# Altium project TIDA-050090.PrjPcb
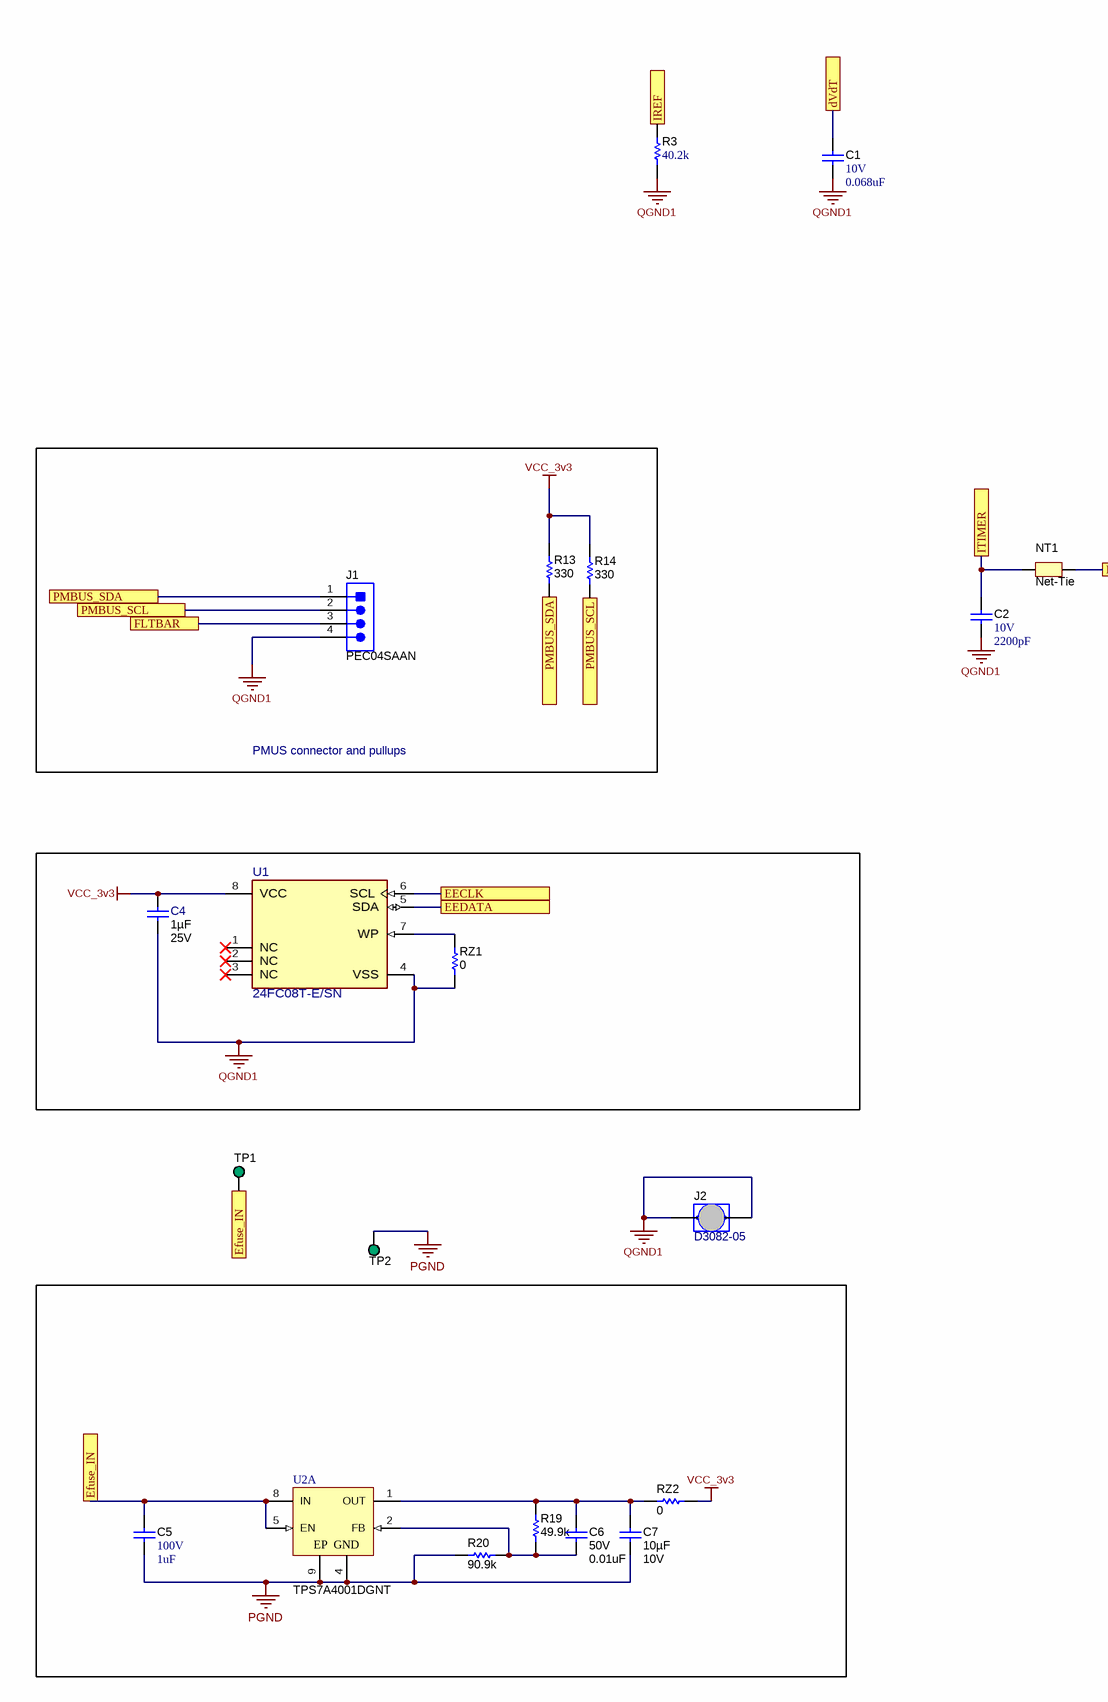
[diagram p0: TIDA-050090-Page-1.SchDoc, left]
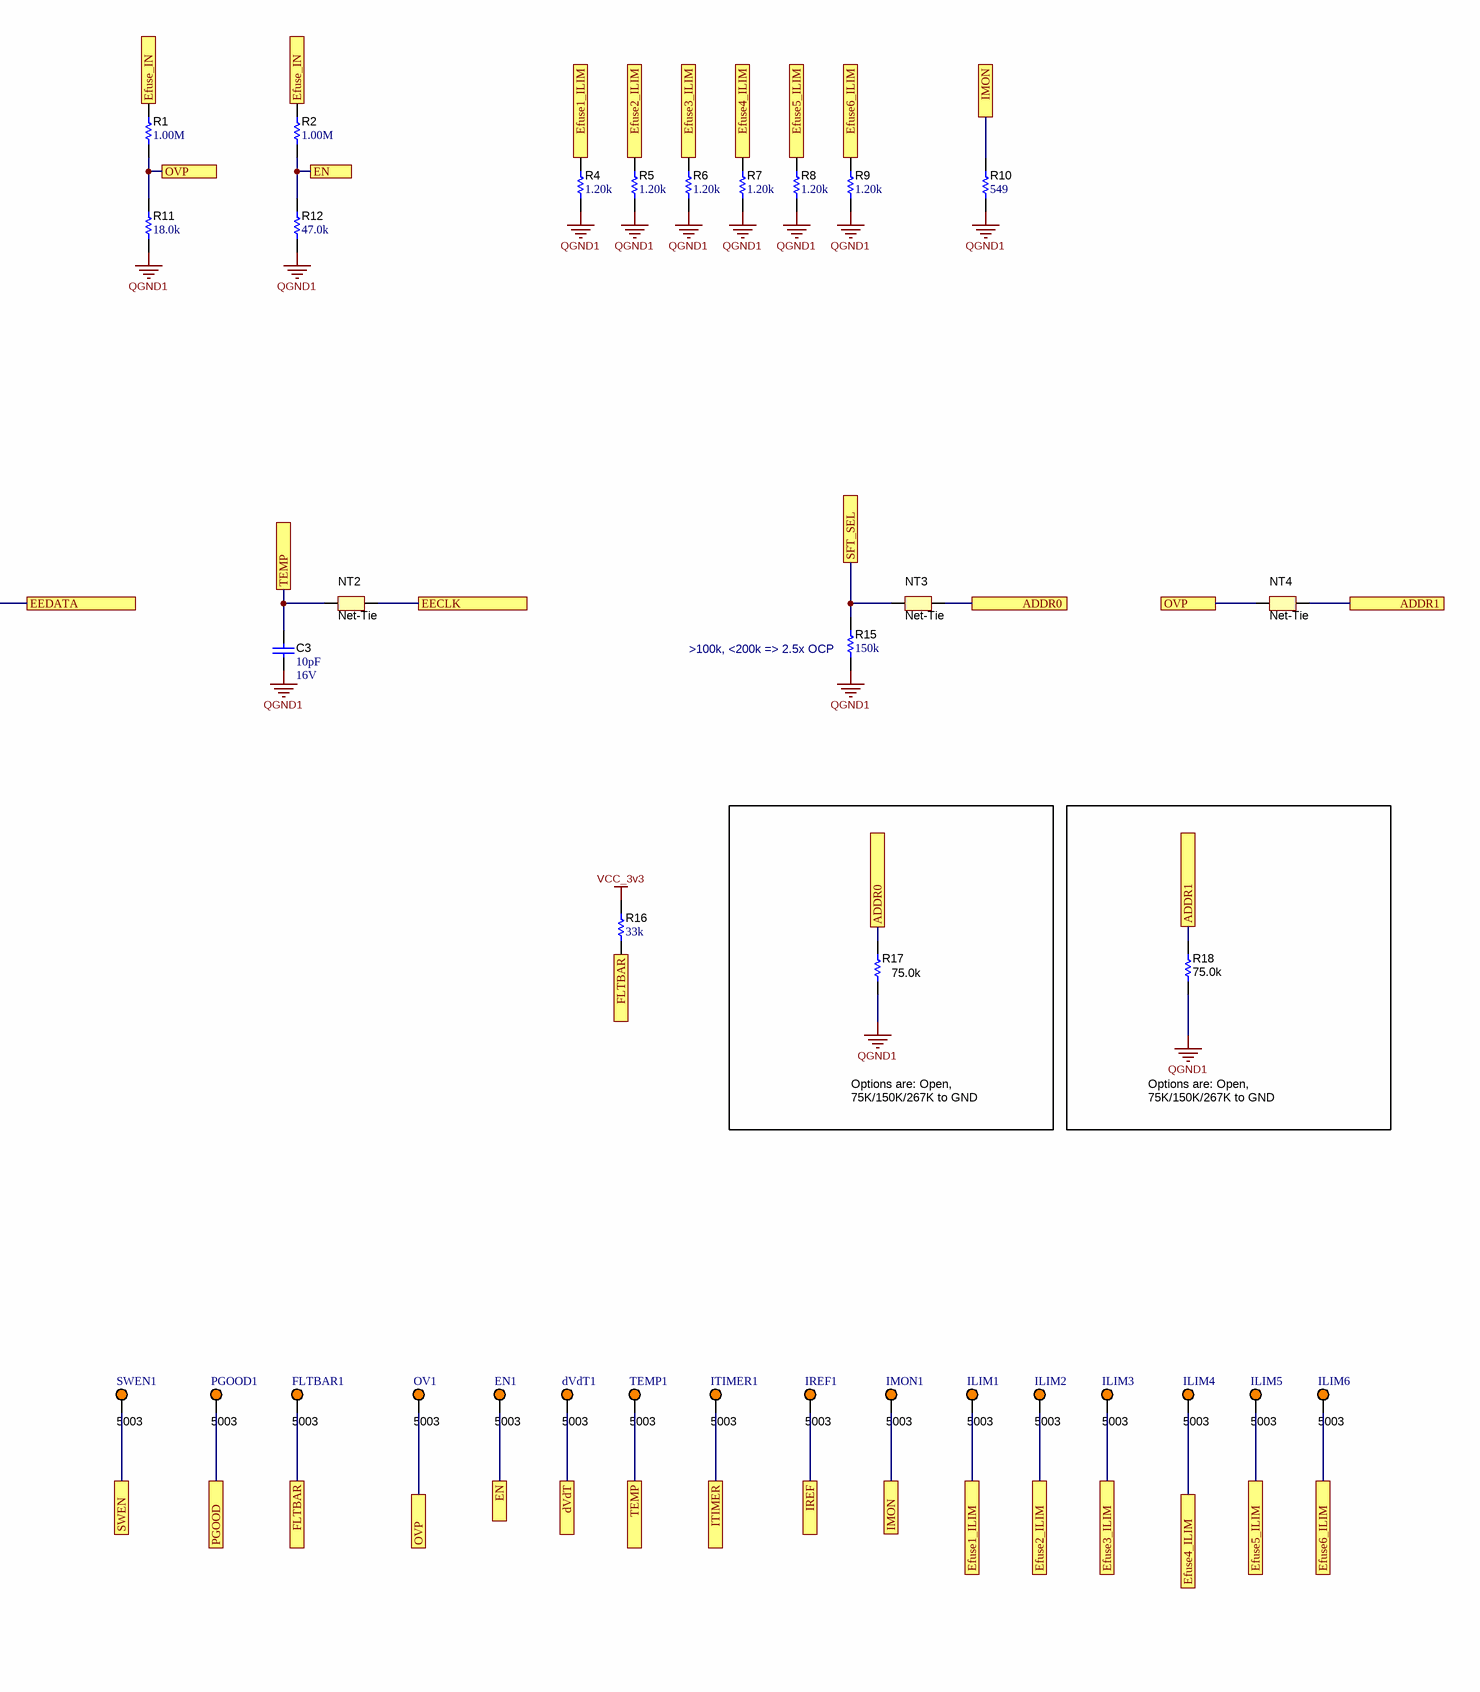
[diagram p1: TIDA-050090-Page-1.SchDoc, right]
CopyrightYear: 2024; PCB_Rev: A; PRJ_Customer: Public Release; PRJ_Engineer: Avishek Pal; PRJ_Number: TIDA-050090; PRJ_Title: TPS1689/5 Reference Design; SCH_Rev: A; TechSupport: http://www.ti.com/support; TID: 050090
3 sheets, 135 parts. Net scope: flat (ports and power ports of the same name join across sheets).
Board file: TIDA-050090.PcbDoc
Sheets:
  TIDA-050090-Page-1.SchDoc
  TIDA-050090-Page-2.SchDoc
  TIDA-050090-Hardware.SchDoc

## Sheet TIDA-050090-Page-1.SchDoc
size A2; Date: Not shown in title block; ApprovedBy: Not shown in title block; CheckedBy: Not shown in title block; Author: Not shown in title block; CompanyName: Not shown in title block; Engineer: Not shown in title block; Organization: Not shown in title block; Address1: Not shown in title block; Address2: Not shown in title block; Address3: Not shown in title block; Address4: Not shown in title block; DocumentNumber: 1; Revision: Use project parameter SCH_Rev; SheetNumber: 1; SheetTotal: 3; PageSetup: Record=PageOptions¦CenterHorizontal=True¦CenterVertical=True¦PrintScale=0.69¦XCorrection=1.00¦YCorrection=1.00¦PrintKind=0¦BorderSize=5000000¦LeftOffset=0¦BottomOffset=0¦Orientation=2¦PaperLength=1000¦PaperWidth=1000¦Scale=100¦PaperSource=15¦PrintQuality=600¦MediaType=1¦DitherType=10¦PaperKind=Letter¦PrintScaleMode=1

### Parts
C1  VDC_V: 10V  ValueDisplayed: 0.068uF  [0402]  (hidden comment: GRM155R61A683KA01D)
C2  VDC_V: 10V  ValueDisplayed: 2200pF  [0402]  (hidden comment: GRM155R61A222KA01D)
C3  Cap_F: 10pF  VDC_V: 16V  [0402]  (hidden comment: C0402C100K4GACTU)
C4  Cap_F: 1µF  VDC_V: 25V  [0603]  (hidden comment: GRJ188R71E105KE11D)
C5  VDC_V: 100V  ValueDisplayed: 1uF  [0805_HV]  (hidden comment: CGA4J3X7S2A105K125AB)
C6  VDC_V: 50V  ValueDisplayed: 0.01uF  [0402]  (hidden comment: GCM155R71H103KA55D)
C7  Cap_F: 10µF  VDC_V: 10V  [0805_HV]  (hidden comment: C0805C106J8RACAUTO)
dVdT1  5003  [Keystone5003]
EN1  5003  [Keystone5003]
FLTBAR1  5003  [Keystone5003]
ILIM1  5003  [Keystone5003]
ILIM2  5003  [Keystone5003]
ILIM3  5003  [Keystone5003]
ILIM4  5003  [Keystone5003]
ILIM5  5003  [Keystone5003]
ILIM6  5003  [Keystone5003]
IMON1  5003  [Keystone5003]
IREF1  5003  [Keystone5003]
ITIMER1  5003  [Keystone5003]
J1  PEC04SAAN  [SULLINS_PEC04SAAN]
J2  D3082-05  [Harwin_D3082-05]
NT1  Net-Tie  [Net-Tie_0805_HV_NoOverlay]  (net tie, no BOM)
NT2  Net-Tie  [Net-Tie_0805_HV_NoOverlay]  (net tie, no BOM)
NT3  Net-Tie  [Net-Tie_0805_HV_NoOverlay]  (net tie, no BOM)
NT4  Net-Tie  [Net-Tie_0805_HV_NoOverlay]  (net tie, no BOM)
OV1  5003  [Keystone5003]
PGOOD1  5003  [Keystone5003]
R1  ValueDisplayed: 1.00M  [0201]  (hidden comment: RK73H1HTTC1004F)
R2  ValueDisplayed: 1.00M  [0201]  (hidden comment: RK73H1HTTC1004F)
R3  ValueDisplayed: 40.2k  [0201]  (hidden comment: RC0201FR-0740K2L)
R4  ValueDisplayed: 1.20k  [0201]  (hidden comment: RC0201DR-071K2L)
R5  ValueDisplayed: 1.20k  [0201]  (hidden comment: RC0201DR-071K2L)
R6  ValueDisplayed: 1.20k  [0201]  (hidden comment: RC0201DR-071K2L)
R7  ValueDisplayed: 1.20k  [0201]  (hidden comment: RC0201DR-071K2L)
R8  ValueDisplayed: 1.20k  [0201]  (hidden comment: RC0201DR-071K2L)
R9  ValueDisplayed: 1.20k  [0201]  (hidden comment: RC0201DR-071K2L)
R10  ValueDisplayed: 549  [0201]  (hidden comment: RC0201FR-07549RL)
R11  ValueDisplayed: 18.0k  [0201]  (hidden comment: RC0201FR-0718KL)
R12  ValueDisplayed: 47.0k  [0201]  (hidden comment: RC0201FR-7D47KL)
R13  ValueDisplayed: 330  [0402]  (hidden comment: ERJ-2RKF3300X)
R14  ValueDisplayed: 330  [0402]  (hidden comment: ERJ-2RKF3300X)
R15  ValueDisplayed: 150k  [0201]  (hidden comment: RC0201FR-7D150KL)
R16  ValueDisplayed: 33k  [0201]  (hidden comment: RC0201JR-0733KL)
R17  ValueDisplayed: 75.0k  [0402]  (hidden comment: CRCW040275K0FKED)
R18  ValueDisplayed: 75.0k  [0402]  (hidden comment: CRCW040275K0FKED)
R19  ValueDisplayed: 49.9k  [0402]  (hidden comment: CRCW040249K9FKED)
R20  ValueDisplayed: 90.9k  [0402]  (hidden comment: CRCW040290K9FKED)
RZ1  ValueDisplayed: 0  [0402]  (hidden comment: CRCW04020000Z0ED)
RZ2  ValueDisplayed: 0  [0402]  (hidden comment: CRCW04020000Z0ED)
SWEN1  5003  [Keystone5003]
TEMP1  5003  [Keystone5003]
TP1  (no value)  [Keystone5126]
TP2  (no value)  [Keystone5126]
U1  24FC08T-E/SN  [FP-24FC08T-E_SN_SOIC8-MFG]
U2  TPS7A4001DGNT  [DGN0008B_N]  (part A of 2)

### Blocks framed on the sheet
PMUS connector and pullups: J1 R13 R14

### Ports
ADDR0, ADDR1, dVdT, EECLK, EEDATA, Efuse1_ILIM, Efuse2_ILIM, Efuse3_ILIM, Efuse4_ILIM, Efuse5_ILIM, Efuse6_ILIM, Efuse_IN, EN, FLTBAR, IMON, IREF, ITIMER, OVP, PGOOD, PMBUS_SCL, PMBUS_SDA, SFT_SEL, SWEN, TEMP

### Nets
PGND: C5.2 C7.2 R20.1 TP2.1 U2.4(GND) U2.9(EP)
QGND1: C1.2 C2.2 C3.2 C4.2 J1.4 J2.1 J2.2 R3.1 R4.1 R5.1 R6.1 R7.1 R8.1 R9.1 R10.1 R11.1 R12.1 R15.1 R17.1 R18.1 RZ1.1 U1.4(VSS)
VCC_3v3: C4.1 R13.2 R14.2 R16.2 RZ2.1 U1.8(VCC)
ADDR0: NT3.2 R17.2 ; port ADDR0
ADDR1: NT4.2 R18.2 ; port ADDR1
dVdT: C1.1 dVdT1.1 ; port dVdT
EECLK: NT2.2 U1.6(SCL) ; port EECLK
EEDATA: NT1.2 U1.5(SDA) ; port EEDATA
Efuse1_ILIM: ILIM1.1 R4.2 ; port Efuse1_ILIM
Efuse2_ILIM: ILIM2.1 R5.2 ; port Efuse2_ILIM
Efuse3_ILIM: ILIM3.1 R6.2 ; port Efuse3_ILIM
Efuse4_ILIM: ILIM4.1 R7.2 ; port Efuse4_ILIM
Efuse5_ILIM: ILIM5.1 R8.2 ; port Efuse5_ILIM
Efuse6_ILIM: ILIM6.1 R9.2 ; port Efuse6_ILIM
Efuse_IN: C5.1 R1.2 R2.2 TP1.1 U2.5(EN) U2.8(IN) ; port Efuse_IN
EN: EN1.1 R2.1 R12.2 ; port EN
FLTBAR: FLTBAR1.1 J1.3 R16.1 ; port FLTBAR
IMON: IMON1.1 R10.2 ; port IMON
IREF: IREF1.1 R3.2 ; port IREF
ITIMER: C2.1 ITIMER1.1 NT1.1 ; port ITIMER
OVP: NT4.1 OV1.1 R1.1 R11.2 ; port OVP
PGOOD: PGOOD1.1 ; port PGOOD
PMBUS_SCL: J1.2 R14.1 ; port PMBUS_SCL
PMBUS_SDA: J1.1 R13.1 ; port PMBUS_SDA
SFT_SEL: NT3.1 R15.2 ; port SFT_SEL
SWEN: SWEN1.1 ; port SWEN
TEMP: C3.1 NT2.1 TEMP1.1 ; port TEMP
NetC6_1: C6.1 C7.1 R19.2 RZ2.2 U2.1(OUT)
NetC6_2: C6.2 R19.1 R20.2 U2.2(FB)
NetRZ1_2: RZ1.2 U1.7(WP)

Not connected (* = marked no-connect by the designer): U1 1(NC)* 2(NC)* 3(NC)*

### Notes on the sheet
- (near R15) >100k, <200k => 2.5x OCP
- Options are: Open, 75K/150K/267K to GND

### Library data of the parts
C1 = CMP-0006585-2: CAP, CERM, 0.068 uF, 10 V, +/- 10%, X5R, 0402; Manufacturer: MuRata; TaMin_C: -55°C; Polarized: N; SizeAreaWB_mm2: 3; Value1: Unknown; U/M: EA; TaMax_C: 85°C; SizeZ_mm: 0.6; SizeX_mm: 1; SizeY_mm: 0.5; Cap_F: 68nF; AEC Category: Q200
C2 = CMP-0006569-2: CAP, CERM, 2200 pF, 10 V, +/- 10%, X5R, 0402; Manufacturer: MuRata; TaMin_C: -55°C; Polarized: N; SizeAreaWB_mm2: 3; Value1: Unknown; U/M: EA; Value: 2200pF; TaMax_C: 85°C; SizeZ_mm: 0.6; SizeX_mm: 1; SizeY_mm: 0.5; Cap_F: 2.2nF; AEC Category: Q200
C3 = CMP-0079539-1: CAP, CERM, 10 pF, 16 V,+/- 10%, C0G, 0402; Manufacturer: Kemet; SizeAreaWB_mm2: 3; SizeArea_mm2: 0.5; AEC Qualified: N; AEC Category: Q200; Value: 10pF; TaMax_C: 125°C; SizeZ_mm: 0.6; Green_REACh: Passed; TaMin_C: -55°C; Green_Lifecycle: Active; U/M: EA; SizeX_mm: 1
C4 = CMP-0079720-1: CAP, CERM, 1 µF, 25 V,+/- 10%, X7R, 0603; Manufacturer: MuRata; TaMin_C: -55°C; Polarized: N; SizeAreaWB_mm2: 4.68; U/M: EA; Value: 1uF; TaMax_C: 125°C; SizeZ_mm: 1; SizeX_mm: 1.6; SizeY_mm: 0.8; SizeArea_mm2: 1.28; AEC Category: Q200
C5 = CMP-0007980-1: CAP, CERM, 1 uF, 100 V, +/- 10%, X7S, AEC-Q200 Grade 1, 0805; Manufacturer: TDK; TaMin_C: -55°C; ESR_ohm: 8.255m; Polarized: N; SizeAreaWB_mm2: 6.75; Value1: 0.008255 ohm; U/M: EA; Value: 1uF; TaMax_C: 125°C; SizeZ_mm: 1.45; SizeX_mm: 2; SizeY_mm: 1.25; Cap_Case: 0805; SizeArea_mm2: 2.5; AEC Qualified: Y; Cap_F: 1µF; IRMS_A: 2.2744A; AEC Grade: 1; AEC Category: Q200
C6 = CMP-0006355-1: CAP, CERM, 0.01 uF, 50 V, +/- 10%, C0G/NP0, 0402; Manufacturer: MuRata; TaMin_C: -55°C; Polarized: N; SizeAreaWB_mm2: 3; Value1: Unknown; U/M: EA; Value: 0.01uF; TaMax_C: 125°C; SizeZ_mm: 0.6; SizeX_mm: 1; SizeY_mm: 0.5; Cap_F: 10nF; AEC Category: Q200
C7 = CMP-0081061-1: CAP, CERM, 10 µF, 10 V,+/- 5%, X7R, AEC-Q200 Grade 1, 0805; Manufacturer: Kemet; TaMin_C: -55°C; Polarized: N; SizeAreaWB_mm2: 6.75; U/M: EA; Value: 10uF; TaMax_C: 125°C; SizeZ_mm: 1.45; SizeX_mm: 2; SizeY_mm: 1.25; Cap_Case: 0805; SizeArea_mm2: 2.5; AEC Qualified: Y; AEC Grade: 1; AEC Category: Q200
dVdT1 EN1 FLTBAR1 ILIM1-ILIM6 IMON1 IREF1 ITIMER1 OV1 PGOOD1 SWEN1 TEMP1 = CMP-0055140-1: Test Point, Miniature, Orange, TH; Manufacturer: Keystone; CNHeader: FALSE; Green_Lifecycle: Active; Green_REACh: Passed; ContactFinish: Silver; CT: TRUE
J1 = CMP-0054562-1: Header, 100mil, 4x1, Tin, TH; Manufacturer: Sullins Connector Solutions; CNHeader: TRUE; Current_A: 3A; Green_Lifecycle: Not Set; Shrouded: N; Gender: Male; Green_REACh: Incomplete; Voltage_V: 1.8kV; Row_Count: 1; Pitch_mm: 2.54; CT: FALSE; Cert_UL: Y
J2 = CMP-0075110-1: 1mm Uninsulated Shorting Plug, 10.16mm spacing, TH; Manufacturer: Harwin; CNHeader: False; Green_Lifecycle: Active; Green_REACh: Passed; CompType: Jumper Wire
NT1-NT4 = CMP-0078142-6: Single point connection between nets.
R1 R2 = CMP-0028122-1: RES, 1.00 M, 1%, 0.05 W, AEC-Q200 Grade 0, 0201; Manufacturer: KOA Speer; Power_W: 50mW; TempCo: 200 ppm/C; Value_Code: 1M00; U/M: EA; Value: 1.00Meg; EIA_Code: E96; Res_ohm: 1M; SizeX_mm: 0.6; SizeY_mm: 0.3; SizeZ_mm: 0.26; Value2: 0.05W; SizeArea_mm2: 0.18; AEC Qualified: Y; VDC_V: 25V; AEC Grade: 0; AEC Category: Q200
R3 = CMP-0027688-1: RES, 40.2 k, 1%, 0.05 W, 0201; Manufacturer: Yageo America; Power_W: 50mW; TempCo: 200 ppm/C; Value_Code: 40k2; U/M: EA; Value: 40.2k; EIA_Code: E96; SizeX_mm: 0.6; SizeY_mm: 0.3; SizeZ_mm: 0.26; Value2: 0.05W; SizeArea_mm2: 0.18; AEC Qualified: N; VDC_V: 25V; AEC Category: Q200
R4-R9 = CMP-0028147-1: RES, 1.20 k, 0.5%, 0.05 W, 0201; Manufacturer: Yageo America; Power_W: 50mW; TempCo: 200 ppm/C; Value_Code: 1k20; U/M: EA; Value: 1.20k; EIA_Code: E192; Res_ohm: 1.2k; SizeX_mm: 0.6; SizeY_mm: 0.3; SizeZ_mm: 0.26; Value2: 0.05W; SizeArea_mm2: 0.18; AEC Qualified: N; VDC_V: 25V; AEC Category: Q200
R10 = CMP-0027769-1: RES, 549, 1%, 0.05 W, 0201; Manufacturer: Yageo America; Power_W: 50mW; TempCo: 200 ppm/C; Value_Code: 549R; U/M: EA; Value: 549; EIA_Code: E96; SizeX_mm: 0.6; SizeY_mm: 0.3; SizeZ_mm: 0.26; Value2: 0.05W; SizeArea_mm2: 0.18; AEC Qualified: N; VDC_V: 25V; AEC Category: Q200
R11 = CMP-0027410-1: RES, 18.0 k, 1%, 0.05 W, 0201; Manufacturer: Yageo America; Power_W: 50mW; TempCo: 200 ppm/C; Value_Code: 18k0; U/M: EA; Value: 18.0k; Res_ohm: 18k; SizeX_mm: 0.6; SizeY_mm: 0.3; SizeZ_mm: 0.26; Value2: 0.05W; SizeArea_mm2: 0.18; AEC Qualified: N; VDC_V: 25V; AEC Category: Q200
R12 = CMP-0028024-1: RES, 47.0 k, 1%, 0.05 W, 0201; Manufacturer: Yageo America; Power_W: 50mW; TempCo: 200 ppm/C; Value_Code: 47k0; U/M: EA; Value: 47.0k; Res_ohm: 47k; SizeX_mm: 0.6; SizeY_mm: 0.3; SizeZ_mm: 0.26; Value2: 0.05W; SizeArea_mm2: 0.18; AEC Qualified: N; VDC_V: 25V; AEC Category: Q200
R13 R14 = CMP-0026694-1: RES, 330, 1%, 0.1 W, AEC-Q200 Grade 0, 0402; Manufacturer: Panasonic; Power_W: 100mW; TempCo: 100 ppm/C; Value_Code: 330R; U/M: EA; Value: 330; SizeX_mm: 1; SizeY_mm: 0.5; SizeZ_mm: 0.6; Value2: 0.1W; AEC Qualified: Y; VDC_V: 50V; AEC Grade: 0; AEC Category: Q200
R15 = CMP-0027959-1: RES, 150 k, 1%, 0.05 W, 0201; Manufacturer: Yageo America; Power_W: 50mW; TempCo: 200 ppm/C; U/M: EA; Value: 150k; EIA_Code: E96; SizeX_mm: 0.6; SizeY_mm: 0.3; SizeZ_mm: 0.26; Value2: 0.05W; SizeArea_mm2: 0.18; AEC Qualified: N; VDC_V: 25V; AEC Category: Q200
R16 = CMP-0027101-1: RES, 33 k, 5%, 0.05 W, 0201; Manufacturer: Yageo America; Power_W: 50mW; TempCo: 200 ppm/C; Value_Code: 33k0; U/M: EA; Value: 33k; EIA_Code: E24; SizeX_mm: 0.6; SizeY_mm: 0.3; SizeZ_mm: 0.26; Value2: 0.05W; SizeArea_mm2: 0.18; AEC Qualified: N; VDC_V: 25V; AEC Category: Q200
R17 R18 = CMP-0026543-1: RES, 75.0 k, 1%, 0.063 W, 0402; Manufacturer: Vishay-Dale; Power_W: 63mW; TempCo: 100 ppm/C; Value_Code: 75k0; U/M: EA; Value: 75.0k; EIA_Code: E96; Res_ohm: 75k; SizeX_mm: 1; SizeY_mm: 0.5; SizeZ_mm: 0.6; Value2: 0.063W; VDC_V: 50V; AEC Category: Q200
R19 = CMP-0026403-1: RES, 49.9 k, 1%, 0.063 W, 0402; Manufacturer: Vishay-Dale; Power_W: 63mW; TempCo: 100 ppm/C; Value_Code: 49k9; U/M: EA; Value: 49.9k; EIA_Code: E96; SizeX_mm: 1; SizeY_mm: 0.5; SizeZ_mm: 0.6; Value2: 0.063W; VDC_V: 50V; AEC Category: Q200
R20 = CMP-0026605-1: RES, 90.9 k, 1%, 0.063 W, 0402; Manufacturer: Vishay-Dale; Power_W: 63mW; TempCo: 100 ppm/C; Value_Code: 90k9; U/M: EA; Value: 90.9k; EIA_Code: E96; SizeX_mm: 1; SizeY_mm: 0.5; SizeZ_mm: 0.6; Value2: 0.063W; VDC_V: 50V; AEC Category: Q200
RZ1 RZ2 = CMP-0026822-3: RES, 0, 5%, 0.063 W, AEC-Q200 Grade 0, 0402; Manufacturer: Vishay-Dale; Power_W: 63mW; TempCo: 200 ppm/C; Value_Code: 0000; Value: 0; EIA_Code: E24; SizeX_mm: 1; SizeY_mm: 0.5; SizeZ_mm: 0.6; Value2: 0.063W; AEC Qualified: Y; VDC_V: 50V; AEC Category: Q200
TP1 TP2 = CMP-0055158-1: Test Point, Multipurpose, Green, TH; Manufacturer: Keystone; CNHeader: FALSE; Green_Lifecycle: Active; Green_REACh: Passed; ContactFinish: Silver; CT: TRUE
U1 = CMP-0094711-2: EEPROM Memory IC 8Kb (1K x 8) I²C 1 MHz 450 µs 8-SOIC; Manufacturer: Microchip; Frequency_Fixed: 400kHz; SizeZ_mm: 1.75mm; Nominal Supply Current: 1-3mA; TaMax_C: +125°C; Min Supply Voltage: 1.7V; Access Time: 450ns; Interface: I2C; AEC Qualified: Yes; Standoff Height: 0.1mm; Memory Size: 8Kbits; TaMin_C: -40°C; Max Supply Voltage: 5.5V; AEC Grade: Grade 1
U2 = CMP-0035947-1: Single Output LDO, 50 mA, Adjustable 1.175 to 90 V Output, 7 to 100 V Input, 8-pin MSOP (DGN), -40 to 125 degC, Green (RoHS & no Sb/Br); Manufacturer: Texas Instruments; Vout Adj(Max)(V): 90; SubFamily: Single Channel LDO; Accuracy(%): 2.5; Vin(Min)(V): 7; Iout(Max)(A): 0.05; Vdo(Typ)(mV): 290; Vout Adj(Min)(V): 1.2; Vin(Max)(V): 100; Iq(Typ)(mA): 0.02

## Sheet TIDA-050090-Page-2.SchDoc
size A2; Date: Not shown in title block; ApprovedBy: Not shown in title block; CheckedBy: Not shown in title block; Author: Not shown in title block; CompanyName: Not shown in title block; Engineer: Not shown in title block; Organization: Not shown in title block; Address1: Not shown in title block; Address2: Not shown in title block; Address3: Not shown in title block; Address4: Not shown in title block; DocumentNumber: 2; Revision: Use project parameter SCH_Rev; SheetNumber: 2; SheetTotal: 3; PageSetup: Record=PageOptions¦CenterHorizontal=True¦CenterVertical=True¦PrintScale=0.69¦XCorrection=1.00¦YCorrection=1.00¦PrintKind=0¦BorderSize=5000000¦LeftOffset=0¦BottomOffset=0¦Orientation=2¦PaperLength=1000¦PaperWidth=1000¦Scale=100¦PaperSource=15¦PrintQuality=600¦MediaType=1¦DitherType=10¦PaperKind=Letter¦PrintScaleMode=1
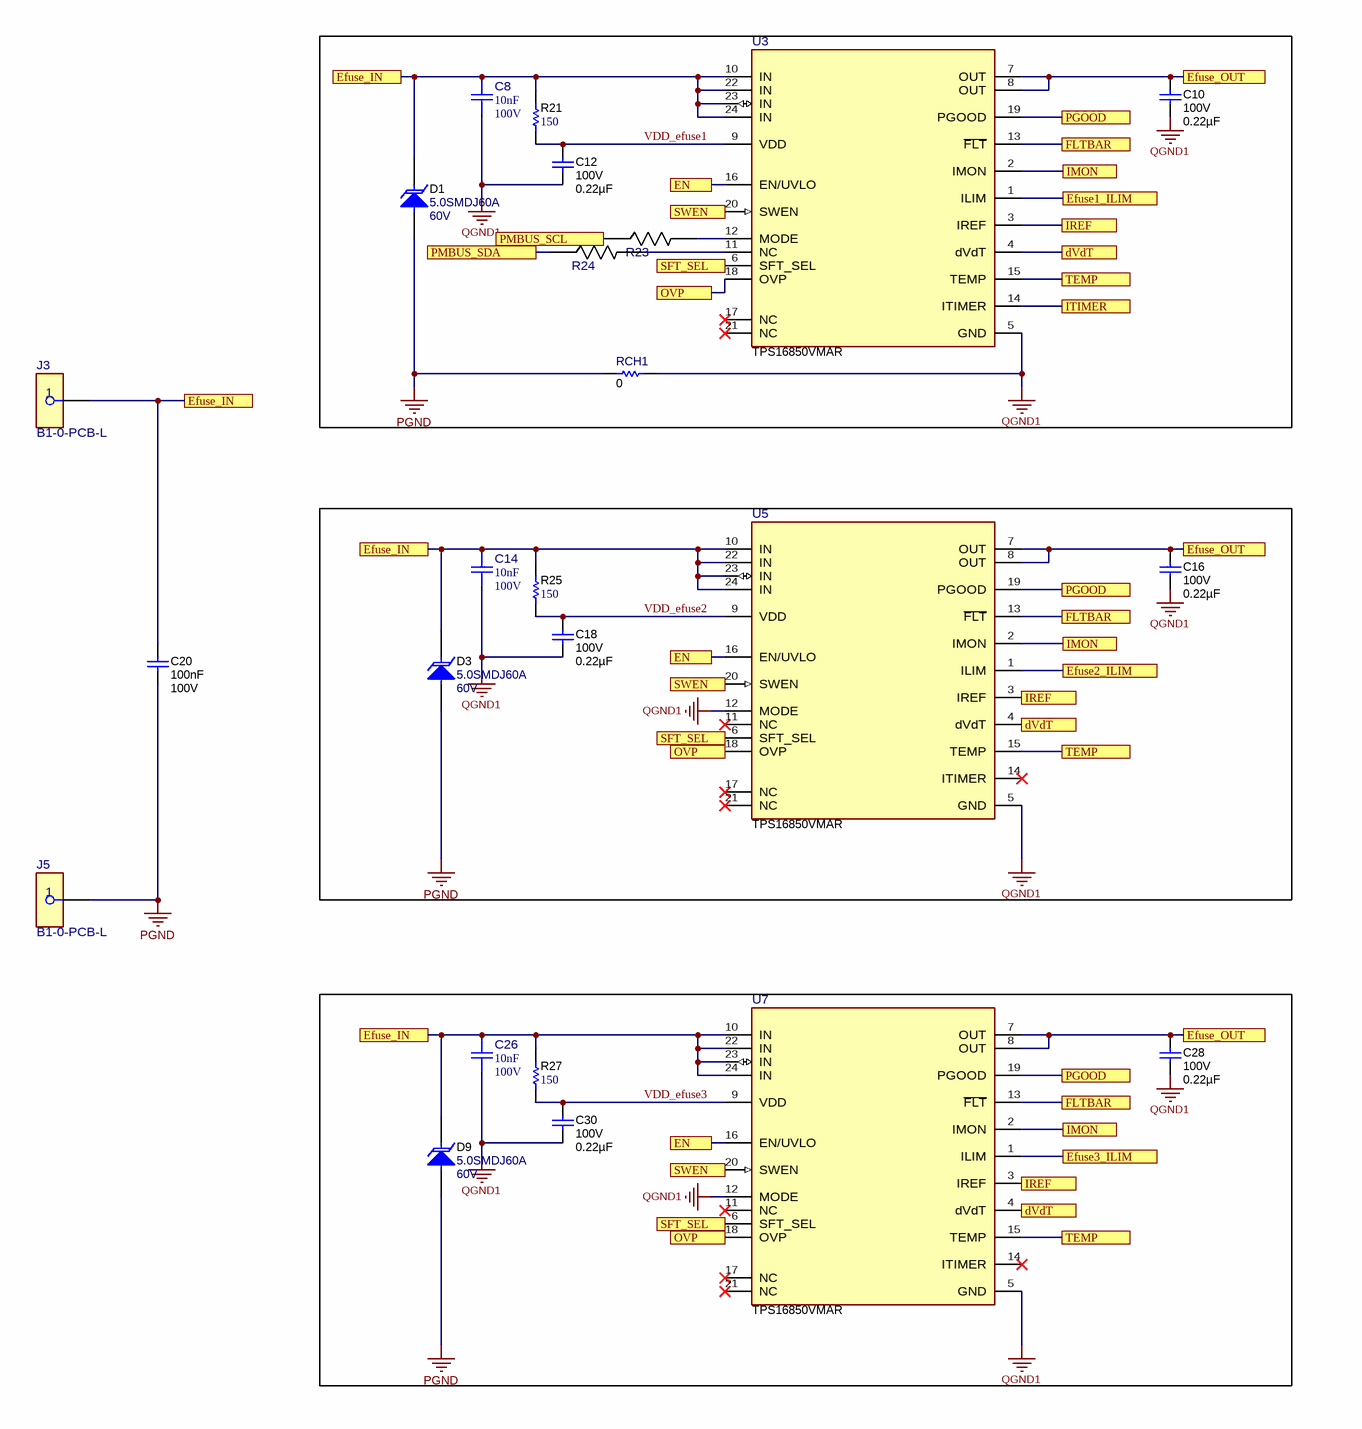
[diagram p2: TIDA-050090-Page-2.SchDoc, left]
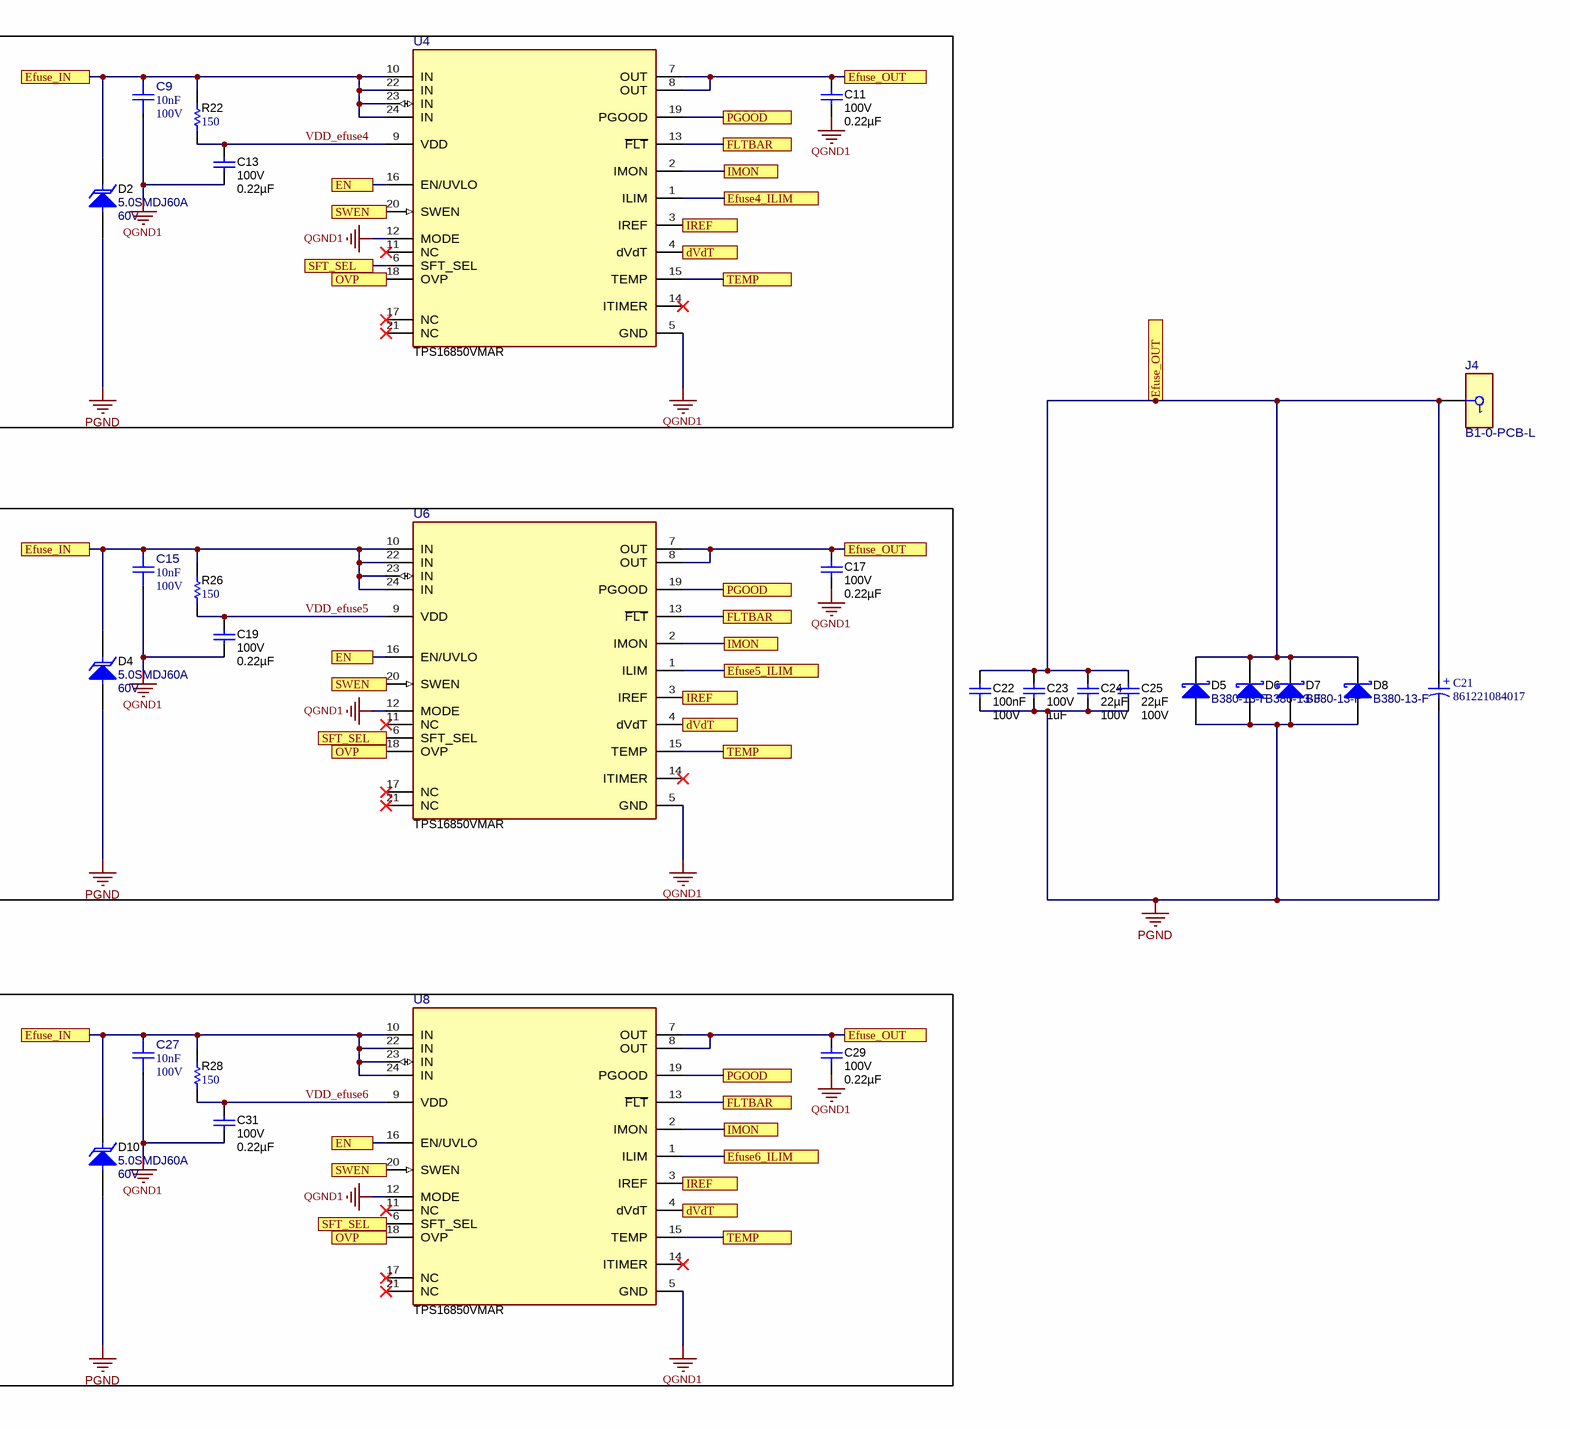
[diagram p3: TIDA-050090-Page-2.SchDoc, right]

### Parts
C8  ValueDisplayed: 10nF  VDC_V: 100V  [FP-C1005X7S2A103K050BB_0402-MFG]  (hidden comment: C1005X7S2A103K050BB)
C9  ValueDisplayed: 10nF  VDC_V: 100V  [FP-C1005X7S2A103K050BB_0402-MFG]  (hidden comment: C1005X7S2A103K050BB)
C10  VDC_V: 100V  ValueDisplayed: 0.22µF  [0603]  (hidden comment: HMK107C7224MAHTE)
C11  VDC_V: 100V  ValueDisplayed: 0.22µF  [0603]  (hidden comment: HMK107C7224MAHTE)
C12  VDC_V: 100V  ValueDisplayed: 0.22µF  [0603]  (hidden comment: HMK107C7224MAHTE)
C13  VDC_V: 100V  ValueDisplayed: 0.22µF  [0603]  (hidden comment: HMK107C7224MAHTE)
C14  ValueDisplayed: 10nF  VDC_V: 100V  [FP-C1005X7S2A103K050BB_0402-MFG]  (hidden comment: C1005X7S2A103K050BB)
C15  ValueDisplayed: 10nF  VDC_V: 100V  [FP-C1005X7S2A103K050BB_0402-MFG]  (hidden comment: C1005X7S2A103K050BB)
C16  VDC_V: 100V  ValueDisplayed: 0.22µF  [0603]  (hidden comment: HMK107C7224MAHTE)
C17  VDC_V: 100V  ValueDisplayed: 0.22µF  [0603]  (hidden comment: HMK107C7224MAHTE)
C18  VDC_V: 100V  ValueDisplayed: 0.22µF  [0603]  (hidden comment: HMK107C7224MAHTE)
C19  VDC_V: 100V  ValueDisplayed: 0.22µF  [0603]  (hidden comment: HMK107C7224MAHTE)
C20  Cap_F: 100nF  VDC_V: 100V  [0603]  (hidden comment: HMK107B7104KAHT)
C21  861221084017  [WCAP-AIE8_D25H40]
C22  Cap_F: 100nF  VDC_V: 100V  [0603]  (hidden comment: HMK107B7104KAHT)
C23  VDC_V: 100V  ValueDisplayed: 1uF  [1210_220]  (hidden comment: C3225X7R2A105K200AA)
C24  ValueDisplayed: 22µF  VDC_V: 100V  [CKG57N]  (hidden comment: CKG57NX7S2A226M500JH)
C25  ValueDisplayed: 22µF  VDC_V: 100V  [CKG57N]  (hidden comment: CKG57NX7S2A226M500JH)
C26  ValueDisplayed: 10nF  VDC_V: 100V  [FP-C1005X7S2A103K050BB_0402-MFG]  (hidden comment: C1005X7S2A103K050BB)
C27  ValueDisplayed: 10nF  VDC_V: 100V  [FP-C1005X7S2A103K050BB_0402-MFG]  (hidden comment: C1005X7S2A103K050BB)
C28  VDC_V: 100V  ValueDisplayed: 0.22µF  [0603]  (hidden comment: HMK107C7224MAHTE)
C29  VDC_V: 100V  ValueDisplayed: 0.22µF  [0603]  (hidden comment: HMK107C7224MAHTE)
C30  VDC_V: 100V  ValueDisplayed: 0.22µF  [0603]  (hidden comment: HMK107C7224MAHTE)
C31  VDC_V: 100V  ValueDisplayed: 0.22µF  [0603]  (hidden comment: HMK107C7224MAHTE)
D1  5.0SMDJ60A  value 60V  [SMC]
D2  5.0SMDJ60A  value 60V  [SMC]
D3  5.0SMDJ60A  value 60V  [SMC]
D4  5.0SMDJ60A  value 60V  [SMC]
D5  B380-13-F  [SMC]
D6  B380-13-F  [SMC]
D7  B380-13-F  [SMC]
D8  B380-13-F  [SMC]
D9  5.0SMDJ60A  value 60V  [SMC]
D10  5.0SMDJ60A  value 60V  [SMC]
J3  B1-0-PCB-L  [FP-B1-0-PCB-L_WIRE_LUG_150A_1-0AWG-MFG]
J4  B1-0-PCB-L  [FP-B1-0-PCB-L_WIRE_LUG_150A_1-0AWG-MFG]
J5  B1-0-PCB-L  [FP-B1-0-PCB-L_WIRE_LUG_150A_1-0AWG-MFG]
R21  ValueDisplayed: 150  [0603]  (hidden comment: CRCW0603150RFKEA)
R22  ValueDisplayed: 150  [0603]  (hidden comment: CRCW0603150RFKEA)
R23  RC0201JR-070RL  [FP-RC0201JR-070RL_0201 (0603 Metric)-MFG]  (value not drawn)
R24  RC0201JR-070RL  [FP-RC0201JR-070RL_0201 (0603 Metric)-MFG]  (value not drawn)
R25  ValueDisplayed: 150  [0603]  (hidden comment: CRCW0603150RFKEA)
R26  ValueDisplayed: 150  [0603]  (hidden comment: CRCW0603150RFKEA)
R27  ValueDisplayed: 150  [0603]  (hidden comment: CRCW0603150RFKEA)
R28  ValueDisplayed: 150  [0603]  (hidden comment: CRCW0603150RFKEA)
RCH1  ValueDisplayed: 0  [0805_HV]  (hidden comment: CRCW08050000Z0EA)
U3  TPS16850VMAR  [VMA0023A-MFG]
U4  TPS16850VMAR  [VMA0023A-MFG]
U5  TPS16850VMAR  [VMA0023A-MFG]
U6  TPS16850VMAR  [VMA0023A-MFG]
U7  TPS16850VMAR  [VMA0023A-MFG]
U8  TPS16850VMAR  [VMA0023A-MFG]

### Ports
dVdT, Efuse1_ILIM, Efuse2_ILIM, Efuse3_ILIM, Efuse4_ILIM, Efuse5_ILIM, Efuse6_ILIM, Efuse_IN, Efuse_OUT, EN, FLTBAR, IMON, IREF, ITIMER, OVP, PGOOD, PMBUS_SCL, PMBUS_SDA, SFT_SEL, SWEN, TEMP

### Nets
PGND: C20.2 C21.2(N) C22.1 C23.1 C24.2 C25.2 D1.2(A) D2.2(A) D3.2(A) D4.2(A) D5.2(A) D6.2(A) D7.2(A) D8.2(A) D9.2(A) D10.2(A) J5.1 RCH1.2
QGND1: C8.1 C9.1 C10.2 C11.2 C12.2 C13.2 C14.1 C15.1 C16.2 C17.2 C18.2 C19.2 C26.1 C27.1 C28.2 C29.2 C30.2 C31.2 RCH1.1 U3.5(GND) U4.5(GND) U4.12(MODE) U5.5(GND) U5.12(MODE) U6.5(GND) U6.12(MODE) U7.5(GND) U7.12(MODE) U8.5(GND) U8.12(MODE)
dVdT: U3.4(dVdT) U4.4(dVdT) U5.4(dVdT) U6.4(dVdT) U7.4(dVdT) U8.4(dVdT) ; port dVdT
Efuse1_ILIM: U3.1(ILIM) ; port Efuse1_ILIM
Efuse2_ILIM: U5.1(ILIM) ; port Efuse2_ILIM
Efuse3_ILIM: U7.1(ILIM) ; port Efuse3_ILIM
Efuse4_ILIM: U4.1(ILIM) ; port Efuse4_ILIM
Efuse5_ILIM: U6.1(ILIM) ; port Efuse5_ILIM
Efuse6_ILIM: U8.1(ILIM) ; port Efuse6_ILIM
Efuse_IN: C8.2 C9.2 C14.2 C15.2 C20.1 C26.2 C27.2 D1.1(K) D2.1(K) D3.1(K) D4.1(K) D9.1(K) D10.1(K) J3.1 R21.2 R22.2 R25.2 R26.2 R27.2 R28.2 U3.10(IN) U3.22(IN) U3.23(IN) U3.24(IN) U4.10(IN) U4.22(IN) U4.23(IN) U4.24(IN) U5.10(IN) U5.22(IN) U5.23(IN) U5.24(IN) U6.10(IN) U6.22(IN) U6.23(IN) U6.24(IN) U7.10(IN) U7.22(IN) U7.23(IN) U7.24(IN) U8.10(IN) U8.22(IN) U8.23(IN) U8.24(IN) ; port Efuse_IN
Efuse_OUT: C10.1 C11.1 C16.1 C17.1 C21.1(P) C22.2 C23.2 C24.1 C25.1 C28.1 C29.1 D5.1(K) D6.1(K) D7.1(K) D8.1(K) J4.1 U3.7(OUT) U3.8(OUT) U4.7(OUT) U4.8(OUT) U5.7(OUT) U5.8(OUT) U6.7(OUT) U6.8(OUT) U7.7(OUT) U7.8(OUT) U8.7(OUT) U8.8(OUT) ; port Efuse_OUT
EN: U3.16(EN/UVLO) U4.16(EN/UVLO) U5.16(EN/UVLO) U6.16(EN/UVLO) U7.16(EN/UVLO) U8.16(EN/UVLO) ; port EN
FLTBAR: U3.13(~{FLT}) U4.13(~{FLT}) U5.13(~{FLT}) U6.13(~{FLT}) U7.13(~{FLT}) U8.13(~{FLT}) ; port FLTBAR
IMON: U3.2(IMON) U4.2(IMON) U5.2(IMON) U6.2(IMON) U7.2(IMON) U8.2(IMON) ; port IMON
IREF: U3.3(IREF) U4.3(IREF) U5.3(IREF) U6.3(IREF) U7.3(IREF) U8.3(IREF) ; port IREF
ITIMER: U3.14(ITIMER) ; port ITIMER
OVP: U3.18(OVP) U4.18(OVP) U5.18(OVP) U6.18(OVP) U7.18(OVP) U8.18(OVP) ; port OVP
PGOOD: U3.19(PGOOD) U4.19(PGOOD) U5.19(PGOOD) U6.19(PGOOD) U7.19(PGOOD) U8.19(PGOOD) ; port PGOOD
PMBUS_SCL: R23.1 ; port PMBUS_SCL
PMBUS_SDA: R24.1 ; port PMBUS_SDA
SFT_SEL: U3.6(SFT_SEL) U4.6(SFT_SEL) U5.6(SFT_SEL) U6.6(SFT_SEL) U7.6(SFT_SEL) U8.6(SFT_SEL) ; port SFT_SEL
SWEN: U3.20(SWEN) U4.20(SWEN) U5.20(SWEN) U6.20(SWEN) U7.20(SWEN) U8.20(SWEN) ; port SWEN
TEMP: U3.15(TEMP) U4.15(TEMP) U5.15(TEMP) U6.15(TEMP) U7.15(TEMP) U8.15(TEMP) ; port TEMP
VDD_efuse1: C12.1 R21.1 U3.9(VDD)
VDD_efuse2: C18.1 R25.1 U5.9(VDD)
VDD_efuse3: C30.1 R27.1 U7.9(VDD)
VDD_efuse4: C13.1 R22.1 U4.9(VDD)
VDD_efuse5: C19.1 R26.1 U6.9(VDD)
VDD_efuse6: C31.1 R28.1 U8.9(VDD)
NetR23_2: R23.2 U3.12(MODE)
NetR24_2: R24.2 U3.11(NC)

Not connected (* = marked no-connect by the designer): U3 17(NC)* 21(NC)*; U4 11(NC)* 14(ITIMER)* 17(NC)* 21(NC)*; U5 11(NC)* 14(ITIMER)* 17(NC)* 21(NC)*; U6 11(NC)* 14(ITIMER)* 17(NC)* 21(NC)*; U7 11(NC)* 14(ITIMER)* 17(NC)* 21(NC)*; U8 11(NC)* 14(ITIMER)* 17(NC)* 21(NC)*

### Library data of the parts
C8 C9 C14 C15 C26 C27 = CMP-0121600-1: Multilayer Ceramic Capacitors 10nF ±10% 100V X7S SMD 0402; Manufacturer: TDK; AEC Qualified: No; SizeZ_mm: 0.55mm; TempCo: 0.22; Tolerance_%: 0.1%
C10 C11 C16 C17 C28 C29 = CMP-0077895-2: CAP, CERM, 0.22 µF, 100 V,+/- 20%, X7S, AEC-Q200 Grade 1, 0603; Manufacturer: Taiyo Yuden; TaMin_C: -55°C; Polarized: N; SizeAreaWB_mm2: 4.68; U/M: EA; Value: 0.22uF; TaMax_C: 125°C; SizeZ_mm: 1.0; SizeX_mm: 1.6; SizeY_mm: 0.8; SizeArea_mm2: 1.28; AEC Qualified: Y; Cap_F: 220nF; AEC Grade: 1; AEC Category: Q200
C12 C13 C18 C19 C30 C31 = CMP-0077895-3: CAP, CERM, 0.22 µF, 100 V,+/- 20%, X7S, AEC-Q200 Grade 1, 0603; Manufacturer: Taiyo Yuden; TaMin_C: -55°C; Polarized: N; SizeAreaWB_mm2: 4.68; U/M: EA; Value: 0.22uF; TaMax_C: 125°C; SizeZ_mm: 1.0; SizeX_mm: 1.6; SizeY_mm: 0.8; SizeArea_mm2: 1.28; AEC Qualified: Y; Cap_F: 220nF; AEC Grade: 1; AEC Category: Q200
C20 C22 = CMP-0081011-1: CAP, CERM, 0.1 µF, 100 V,+/- 10%, X7R, AEC-Q200 Grade 1, 0603; Manufacturer: Taiyo Yuden; SizeAreaWB_mm2: 4.68; SizeArea_mm2: 1.28; AEC Qualified: Y; AEC Category: Q200; Value: 0.1uF; TaMax_C: 125°C; SizeZ_mm: 1; Polarized: N; TaMin_C: -55°C; SizeY_mm: 0.8; U/M: EA; SizeX_mm: 1.6; ValueDisplayed: 0.1µF
C21 = CMP-0117576-1: WCAP-AIE8 Aluminum Electrolytic Capacitor, Snap-In, D25 x H40mm, 1000µF, 200V; Manufacturer: Wurth Elektronik; Cap_F: 1mF; Capacitance Tolerance: +/-20%; Dissipation Factor: 15%; Endurance: 3000h; Leakage Current: 1341.64uA; Ripple Current: 3280mA; Technical Reference: ANAO400102M200DSIC3C000
C23 = CMP-0009125-1: CAP, CERM, 1 uF, 100 V, +/- 10%, X7R, 1210; Manufacturer: TDK; TaMin_C: -55°C; ESR_ohm: 4.956m; Polarized: N; SizeAreaWB_mm2: 14.7; Value1: 0.004956 ohm; U/M: EA; Value: 1uF; TaMax_C: 125°C; SizeZ_mm: 2.2; SizeX_mm: 3.2; SizeY_mm: 2.5; SizeArea_mm2: 8; Cap_F: 1µF; IRMS_A: 3.30731A; AEC Category: Q200
C24 C25 = CMP-0860250-1: CAP, CERM, 22 µF,  VAC/100 VDC,+/- 20%, X7S, 6x5x5mm; Manufacturer: TDK; IRMS_A: 4.1A; SizeX_mm: 6; SizeArea_mm2: 30; AEC Category: Q200; SizeZ_mm: 5.5; Value: 22uF; TaMax_C: 125°C; TaMin_C: -55°C; U/M: EA; SizeY_mm: 5; AEC Qualified: N; SizeAreaWB_mm2: 56
D1-D4 D9 D10 = CMP-0005717-3: Diode, TVS, Uni, 60 V, 96.8 Vc, SMC; Manufacturer: Littelfuse; Ppk: 5kW; AEC Category: Q101; Vbr_Max: 73.7V; Ipp: 51.7A; Vbr_Min: 66.7V; SizeY_mm: 6.22; RJA_CperW: 75; SizeX_mm: 8.13; SizeAreaWB_mm2: 83.2686; SizeArea_mm2: 50.5686; Value1: 5000W; Vc: 96.8V; SizeZ_mm: 2.6
D5-D8 = CMP-0028422-1: Diode, Schottky, 80 V, 3 A, SMC; Manufacturer: Diodes Inc.; Io_A: 3A; Green_Lifecycle: Active; SizeAreaWB_mm2: 83.2686; Vr_V: 80V; Green_REACh: Passed; TJmax_C: 125°C; U/M: EA; Value: 80V; SizeZ_mm: 2.6; SizeX_mm: 8.13; SizeY_mm: 6.22; Vf_V: 790mV; Value2: 0.79V; SizeArea_mm2: 50.5686; AEC Category: Q101; RJC_CperW: 10
J3-J5 = CMP-0093713-1: 1/0 AWG High AMP PCB Wire Lugs 1/0-8 AWG; Manufacturer: INTERNATIONAL HYDRAULICS; Max Wire Gauge: 0; Current_A: 150A; Conn Gender: Female; AEC Qualified: No; Is Female: yes; ContactFinish: Tin; Min Wire Gauge: 1; Conn Orientation: Horizontal
R21 R22 R25-R28 = CMP-0022061-4: RES, 150, 1%, 0.1 W, 0603; Manufacturer: Vishay-Dale; Power_W: 100mW; TempCo: 100 ppm/C; Value_Code: 150R; U/M: EA; Value: 150; EIA_Code: E96; SizeX_mm: 1.6; SizeY_mm: 0.8; SizeZ_mm: 1; Value2: 0.1W; SizeArea_mm2: 1.28; VDC_V: 75V; AEC Category: Q200
R23 R24 = CMP-0086442-1: RES SMD 0 OHM JUMPER 1/20W 0201; Manufacturer: Yageo; TempCo: 200ppm/°C; Power_W: 50mW; VDC_V: 25V; SizeZ_mm: 0.26mm; Res_ohm: 0; Tolerance_%: 5%; AEC Qualified: No; Symbol Name: SYM-RC0201JR-070RL
RCH1 = CMP-0020442-3: RES, 0, 5%, 0.125 W, AEC-Q200 Grade 0, 0805; Manufacturer: Vishay-Dale; Power_W: 125mW; TempCo: 200 ppm/C; Value_Code: 0000; Value: 0; EIA_Code: E24; SizeX_mm: 2; SizeY_mm: 1.25; SizeZ_mm: 1.45; Value2: 0.125W; SizeArea_mm2: 2.5; AEC Qualified: Y; VDC_V: 150V; AEC Category: Q200
U3-U8 = CMP-0120541-1: 9 - 80 V , 4.3 mΩ, 20 A Stackable eFuse with Accurate & Fast Current Monitor; Manufacturer: Texas Instruments; SizeZ_mm: 1.5mm; AEC Qualified: No; Max Supply Voltage: 80V; Min Supply Voltage: 9V; Number Of Outputs: 1; Standoff Height: 0mm; TJmax_C: +125°C

## Sheet TIDA-050090-Hardware.SchDoc
size 431 x 279 mm; Date: Not shown in title block; ApprovedBy: Not shown in title block; CheckedBy: Not shown in title block; Author: Not shown in title block; CompanyName: Not shown in title block; Engineer: Not shown in title block; Organization: Not shown in title block; Address1: Not shown in title block; Address2: Not shown in title block; Address3: Not shown in title block; Address4: Not shown in title block; DocumentNumber: 3; Revision: Use project parameter SCH_Rev; SheetNumber: 3; SheetTotal: 3; PageSetup: Record=PageOptions¦CenterHorizontal=True¦CenterVertical=True¦PrintScale=1.00¦XCorrection=1.00¦YCorrection=1.00¦PrintKind=0¦BorderSize=5000000¦LeftOffset=0¦BottomOffset=0¦Orientation=2¦PaperLength=1000¦PaperWidth=1000¦Scale=100¦PaperSource=15¦PrintQuality=600¦MediaType=1¦DitherType=10¦PaperKind=Letter¦PrintScaleMode=1
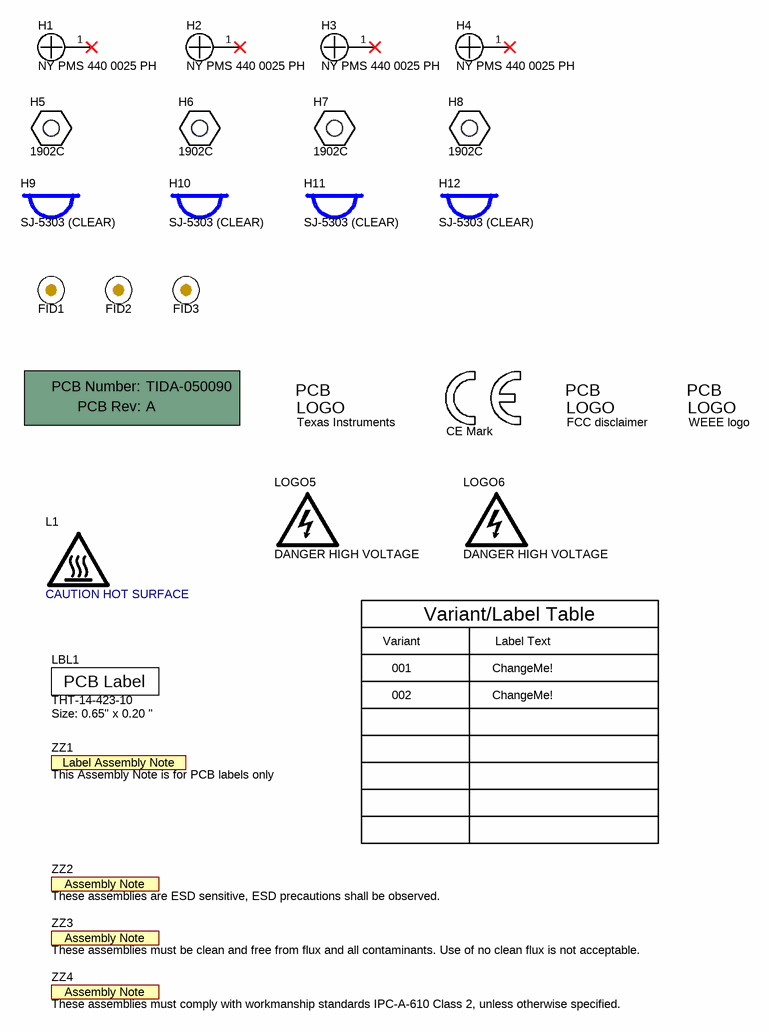
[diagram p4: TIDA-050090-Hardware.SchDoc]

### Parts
!PCB1  Printed Circuit Board  (value not drawn)  (mechanical)
FID1  Fiducial  [Fiducial10-20]  (value not drawn)
FID2  Fiducial  [Fiducial10-20]  (value not drawn)
FID3  Fiducial  [Fiducial10-20]  (value not drawn)
H1  NY PMS 440 0025 PH  [NY PMS 440 0025 PH]
H2  NY PMS 440 0025 PH  [NY PMS 440 0025 PH]
H3  NY PMS 440 0025 PH  [NY PMS 440 0025 PH]
H4  NY PMS 440 0025 PH  [NY PMS 440 0025 PH]
H5  1902C  [Keystone_1902C]
H6  1902C  [Keystone_1902C]
H7  1902C  [Keystone_1902C]
H8  1902C  [Keystone_1902C]
H9  SJ-5303 (CLEAR)  [Bumpon_SJ5003Transparent]
H10  SJ-5303 (CLEAR)  [Bumpon_SJ5003Transparent]
H11  SJ-5303 (CLEAR)  [Bumpon_SJ5003Transparent]
H12  SJ-5303 (CLEAR)  [Bumpon_SJ5003Transparent]
L1  CAUTION HOT SURFACE  [IEC_HotSurface_Small]  (no BOM)
LBL1  THT-14-423-10  Note: Size: 0.65" x 0.20 "  [Label_650x200]
Logo1  CE Mark  [CE_Mark_5mm]  (no BOM)
Logo2  Texas Instruments  [TI_Stacked_Overlay_Small]  (no BOM)
Logo3  FCC disclaimer  [FCC_disclaimer]  (no BOM)
Logo4  WEEE logo  [WEEE_Minimum]  (no BOM)
LOGO5  DANGER HIGH VOLTAGE  [IEC_HighVoltage_Small]  (no BOM)
LOGO6  DANGER HIGH VOLTAGE  [IEC_HighVoltage_Small]  (no BOM)
ZZ1  This Assembly Note is for PCB labels only  [AssemblyNoteLabel]  (no BOM)
ZZ2  These assemblies are ESD sensitive, ESD precautions shall be observed.  [AssemblyNote]  (no BOM)
ZZ3  These assemblies must be clean and free from flux and all contaminants. Use of no clean flux is not acceptable.  [AssemblyNote]  (no BOM)
ZZ4  These assemblies must comply with workmanship standards IPC-A-610 Class 2, unless otherwise specified.  [AssemblyNote]  (no BOM)

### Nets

Not connected (* = marked no-connect by the designer): H1 1*; H2 1*; H3 1*; H4 1*

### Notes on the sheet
- Variant
- Variant/Label Table
- Label Text
- 001
- 002
- ChangeMe!

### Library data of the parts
!PCB1 = CMP-0003618-2: Manufacturer: Any; PartNumber: TIDA-050090
FID1-FID3 = CMP-0077181-1: Fiducial mark.  There is nothing to buy or mount.
H1-H4 = CMP-0003617-1: Machine Screw, Round, #4-40 x 1/4, Nylon, Philips panhead; Manufacturer: B&F Fastener Supply; CompType: Hardware
H5-H8 = CMP-0003610-1: Standoff, Hex, 0.5"L #4-40 Nylon; Manufacturer: Keystone; CompType: Hardware
H9-H12 = CMP-0003620-1: Bumpon, Hemisphere, 0.44 X 0.20, Clear; Manufacturer: 3M
L1 = CMP-0074837-1: IEC 61010-1 Hot Surface Warning; SymbolCreator: a0412235
LBL1 = CMP-0003625-1: Thermal Transfer Printable Labels, 0.650" W x 0.200" H - 10,000 per roll; Manufacturer: Brady; CompType: Label
Logo1 = CMP-0074844-1: SymbolCreator: a0412235
Logo2 = CMP-0074838-1: Texas Instrument Corporate Signature; SymbolCreator: a0412235; Lib Reference: TI_Logo; Library Reference: Logo
Logo3 = CMP-0074847-1: FCC_disclaimer; Library Reference: Logo
Logo4 = CMP-0074769-1
LOGO5 LOGO6 = CMP-0074835-1: IEC 61010-1 High Voltage Warning; SymbolCreator: a0412235
ZZ1 = CMP-0003616-3
ZZ2 = CMP-0077236-1
ZZ3 = CMP-0077237-1
ZZ4 = CMP-0077238-1

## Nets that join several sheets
PGND: TIDA-050090-Page-1 (6 pins), TIDA-050090-Page-2 (18 pins)
QGND1: TIDA-050090-Page-1 (22 pins), TIDA-050090-Page-2 (30 pins)
dVdT: TIDA-050090-Page-1 (C1.1 dVdT1.1), TIDA-050090-Page-2 (6 pins)
Efuse1_ILIM: TIDA-050090-Page-1 (ILIM1.1 R4.2), TIDA-050090-Page-2 (U3.1)
Efuse2_ILIM: TIDA-050090-Page-1 (ILIM2.1 R5.2), TIDA-050090-Page-2 (U5.1)
Efuse3_ILIM: TIDA-050090-Page-1 (ILIM3.1 R6.2), TIDA-050090-Page-2 (U7.1)
Efuse4_ILIM: TIDA-050090-Page-1 (ILIM4.1 R7.2), TIDA-050090-Page-2 (U4.1)
Efuse5_ILIM: TIDA-050090-Page-1 (ILIM5.1 R8.2), TIDA-050090-Page-2 (U6.1)
Efuse6_ILIM: TIDA-050090-Page-1 (ILIM6.1 R9.2), TIDA-050090-Page-2 (U8.1)
Efuse_IN: TIDA-050090-Page-1 (6 pins), TIDA-050090-Page-2 (44 pins)
EN: TIDA-050090-Page-1 (EN1.1 R2.1 R12.2), TIDA-050090-Page-2 (6 pins)
FLTBAR: TIDA-050090-Page-1 (FLTBAR1.1 J1.3 R16.1), TIDA-050090-Page-2 (6 pins)
IMON: TIDA-050090-Page-1 (IMON1.1 R10.2), TIDA-050090-Page-2 (6 pins)
IREF: TIDA-050090-Page-1 (IREF1.1 R3.2), TIDA-050090-Page-2 (6 pins)
ITIMER: TIDA-050090-Page-1 (C2.1 ITIMER1.1 NT1.1), TIDA-050090-Page-2 (U3.14)
OVP: TIDA-050090-Page-1 (NT4.1 OV1.1 R1.1 R11.2), TIDA-050090-Page-2 (6 pins)
PGOOD: TIDA-050090-Page-1 (PGOOD1.1), TIDA-050090-Page-2 (6 pins)
PMBUS_SCL: TIDA-050090-Page-1 (J1.2 R14.1), TIDA-050090-Page-2 (R23.1)
PMBUS_SDA: TIDA-050090-Page-1 (J1.1 R13.1), TIDA-050090-Page-2 (R24.1)
SFT_SEL: TIDA-050090-Page-1 (NT3.1 R15.2), TIDA-050090-Page-2 (6 pins)
SWEN: TIDA-050090-Page-1 (SWEN1.1), TIDA-050090-Page-2 (6 pins)
TEMP: TIDA-050090-Page-1 (C3.1 NT2.1 TEMP1.1), TIDA-050090-Page-2 (6 pins)

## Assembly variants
001: not fitted C21 FID1 FID2 FID3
